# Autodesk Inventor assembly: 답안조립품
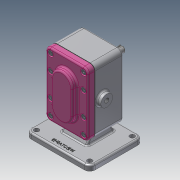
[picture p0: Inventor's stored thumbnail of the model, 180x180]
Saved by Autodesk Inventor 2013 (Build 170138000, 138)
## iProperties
Created: 2020-04
Part Number: 답안조립품
Document SubType Name: Assembly
Designer: CADCOM
Author: CADCOM
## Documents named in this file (11)
- C:\Users\CADCOM\Desktop\700407V1010\답안조립품.iam
- C:\Users\CADCOM\Desktop\700407V1010\본체.ipt
- C:\Users\CADCOM\Desktop\700407V1010\Ű 6 x 6 x 18.ipt
- C:\Users\CADCOM\Desktop\700407V1010\개스킷.ipt
- C:\Users\CADCOM\Desktop\700407V1010\메인축.ipt
- C:\Users\CADCOM\Desktop\700407V1010\베어링부시.ipt
- C:\Users\CADCOM\Desktop\700407V1010\볼트 M5.ipt
- C:\Users\CADCOM\Desktop\700407V1010\서브축.ipt
- C:\Users\CADCOM\Desktop\700407V1010\스퍼기어.ipt
- C:\Users\CADCOM\Desktop\700407V1010\오일 실 16 28 7.ipt
- C:\Users\CADCOM\Desktop\700407V1010\커버.ipt
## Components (3 placed, 2 different names)
1. Ű 6 x 6 x 18:1
2. 개스킷:1
3. Ű 6 x 6 x 18:2
